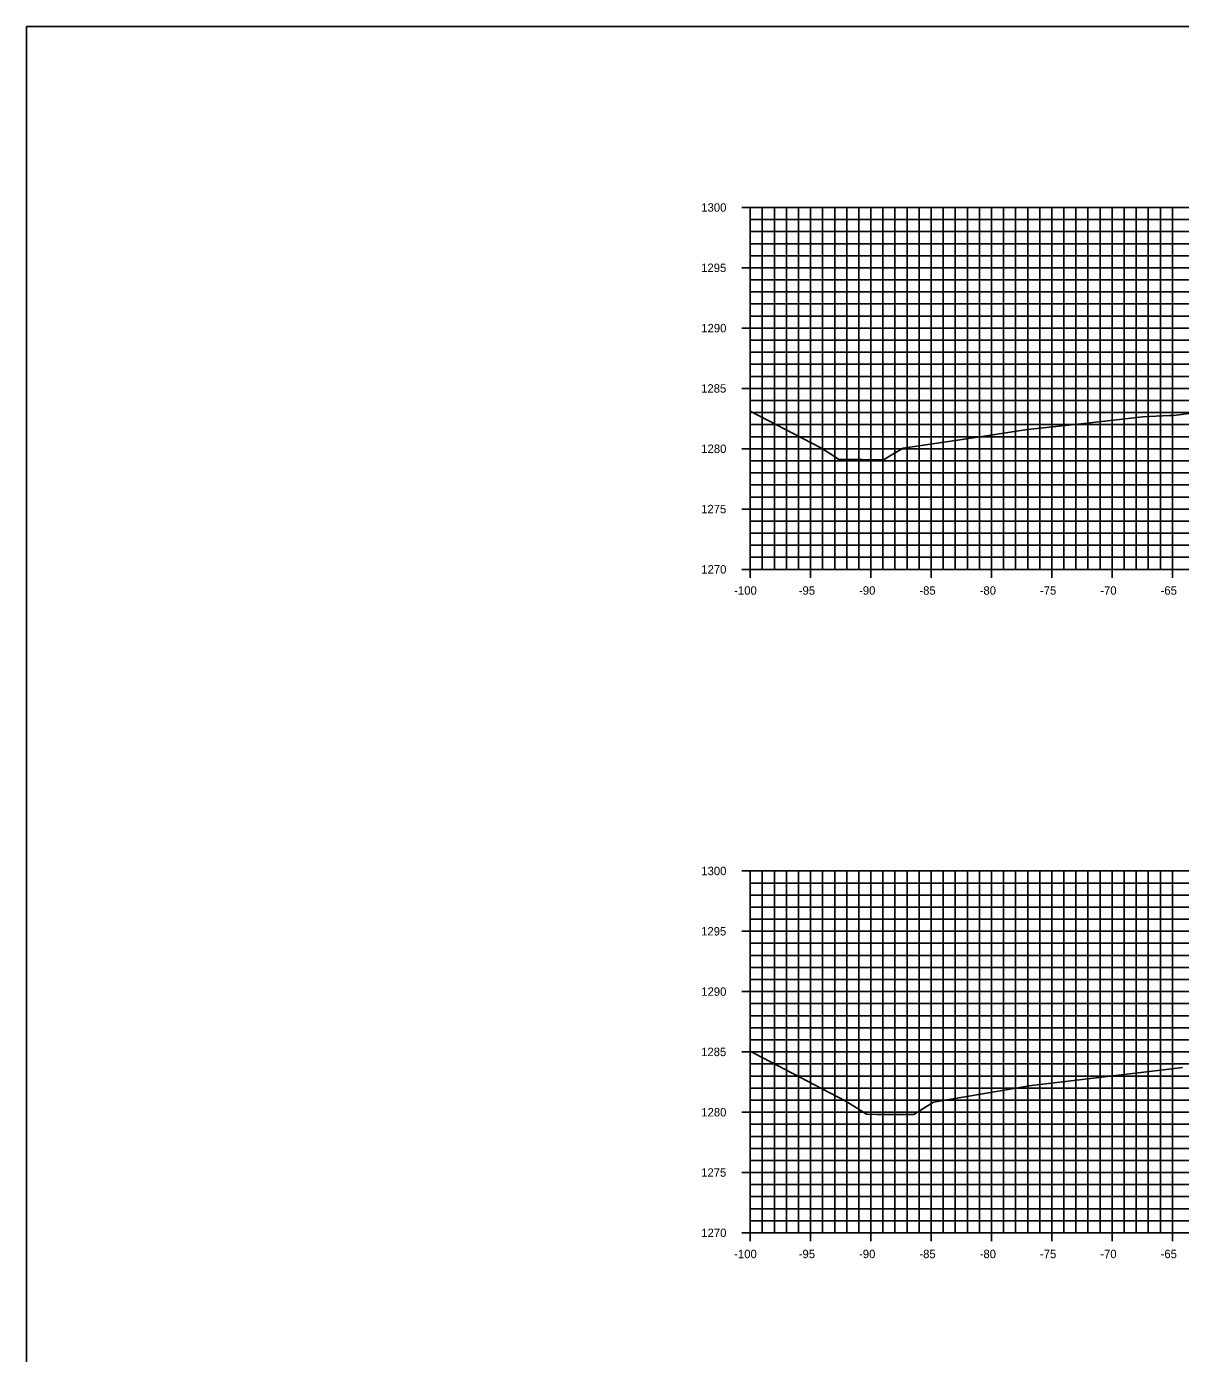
# Model space of a CAD drawing. Extents: x 674939 to 678919, y 750652 to 765176.
# Drawn here: x 678578.5 to 678674.2, y 755632.6 to 755742.6 of the extents above; entities that cross this region are included whole.
import ezdxf

# ---------------------------------------------------------------- set-up
doc = ezdxf.new("R2010")
doc.units = 0
for name, color, linetype in [('Level 10', 7, 'Continuous'), ('Level 20', 7, 'Continuous'), ('Level 4', 7, 'Continuous'), ('Level 8', 7, 'Continuous'), ('Level 9', 7, 'Continuous')]:
    doc.layers.add(name, color=color, linetype=linetype)

msp = doc.modelspace()

# ---------------------------------------------------------------- linework, layer by layer
at = {"layer": 'Level 10'}
for points in [[(678638.53, 755710.67), (678644.37, 755707.63), (678645.04, 755707.2), (678645.84, 755706.68), (678646.81, 755706.67), (678647.78, 755706.65), (678648.66, 755706.64), (678649.59, 755706.64), (678650.36, 755707.11), (678651.22, 755707.61), (678656.66, 755708.41), (678661.52, 755709.14), (678666.22, 755709.65), (678671.08, 755710.2), (678673.25, 755710.31), (678673.43, 755710.32), (678673.47, 755710.32), (678673.63, 755710.32), (678675.14, 755710.49)], [(678638.53, 755657.61), (678638.95, 755657.39), (678646.41, 755653.48), (678647.35, 755652.91), (678648.17, 755652.39), (678649.03, 755652.37), (678649.83, 755652.35), (678650.88, 755652.35), (678652.08, 755652.36), (678652.93, 755652.89), (678653.72, 755653.37), (678660.71, 755654.57), (678661.65, 755654.74), (678662.09, 755654.79), (678670.01, 755655.72), (678671.63, 755655.92), (678674.36, 755656.26)]]:
    msp.add_lwpolyline(points, dxfattribs=at)
at = {"layer": 'Level 20'}
for p, q in [((678638.53, 755727.55), (678838.53, 755727.55)), ((678638.53, 755697.55), (678638.53, 755727.55)), ((678639.53, 755697.55), (678639.53, 755727.55)), ((678640.53, 755697.55), (678640.53, 755727.55)), ((678641.53, 755697.55), (678641.53, 755727.55)), ((678642.53, 755697.55), (678642.53, 755727.55)), ((678643.53, 755697.55), (678643.53, 755727.55)), ((678644.53, 755697.55), (678644.53, 755727.55)), ((678645.53, 755697.55), (678645.53, 755727.55)), ((678646.53, 755697.55), (678646.53, 755727.55)), ((678647.53, 755697.55), (678647.53, 755727.55)), ((678648.53, 755697.55), (678648.53, 755727.55)), ((678649.53, 755697.55), (678649.53, 755727.55)), ((678650.53, 755697.55), (678650.53, 755727.55)), ((678651.53, 755697.55), (678651.53, 755727.55)), ((678652.53, 755697.55), (678652.53, 755727.55)), ((678653.53, 755697.55), (678653.53, 755727.55)), ((678654.53, 755697.55), (678654.53, 755727.55)), ((678655.53, 755697.55), (678655.53, 755727.55)), ((678656.53, 755697.55), (678656.53, 755727.55)), ((678657.53, 755697.55), (678657.53, 755727.55)), ((678658.53, 755697.55), (678658.53, 755727.55)), ((678659.53, 755697.55), (678659.53, 755727.55)), ((678660.53, 755697.55), (678660.53, 755727.55)), ((678661.53, 755697.55), (678661.53, 755727.55)), ((678662.53, 755697.55), (678662.53, 755727.55)), ((678663.53, 755697.55), (678663.53, 755727.55)), ((678664.53, 755697.55), (678664.53, 755727.55)), ((678665.53, 755697.55), (678665.53, 755727.55)), ((678666.53, 755697.55), (678666.53, 755727.55)), ((678667.53, 755697.55), (678667.53, 755727.55)), ((678668.53, 755697.55), (678668.53, 755727.55)), ((678669.53, 755697.55), (678669.53, 755727.55)), ((678670.53, 755697.55), (678670.53, 755727.55)), ((678671.53, 755697.55), (678671.53, 755727.55)), ((678672.53, 755697.55), (678672.53, 755727.55)), ((678673.53, 755697.55), (678673.53, 755727.55)), ((678638.53, 755726.55), (678838.53, 755726.55)), ((678638.53, 755725.55), (678838.53, 755725.55)), ((678638.53, 755724.55), (678838.53, 755724.55)), ((678638.53, 755723.55), (678838.53, 755723.55)), ((678638.53, 755722.55), (678838.53, 755722.55)), ((678638.53, 755721.55), (678838.53, 755721.55)), ((678638.53, 755720.55), (678838.53, 755720.55)), ((678638.53, 755719.55), (678838.53, 755719.55)), ((678638.53, 755718.55), (678838.53, 755718.55)), ((678638.53, 755717.55), (678838.53, 755717.55)), ((678638.53, 755716.55), (678838.53, 755716.55)), ((678638.53, 755715.55), (678838.53, 755715.55)), ((678638.53, 755714.55), (678838.53, 755714.55)), ((678638.53, 755713.55), (678838.53, 755713.55)), ((678638.53, 755712.55), (678838.53, 755712.55)), ((678638.53, 755711.55), (678838.53, 755711.55)), ((678638.53, 755710.55), (678838.53, 755710.55)), ((678638.53, 755709.55), (678838.53, 755709.55)), ((678638.53, 755708.55), (678838.53, 755708.55)), ((678638.53, 755707.55), (678838.53, 755707.55)), ((678638.53, 755706.55), (678838.53, 755706.55)), ((678638.53, 755705.55), (678838.53, 755705.55)), ((678638.53, 755704.55), (678838.53, 755704.55)), ((678638.53, 755703.55), (678838.53, 755703.55)), ((678638.53, 755702.55), (678838.53, 755702.55)), ((678638.53, 755701.55), (678838.53, 755701.55)), ((678638.53, 755700.55), (678838.53, 755700.55)), ((678638.53, 755699.55), (678838.53, 755699.55)), ((678638.53, 755698.55), (678838.53, 755698.55)), ((678638.53, 755697.55), (678838.53, 755697.55)), ((678638.53, 755672.55), (678838.53, 755672.55)), ((678638.53, 755642.55), (678638.53, 755672.55)), ((678639.53, 755642.55), (678639.53, 755672.55)), ((678640.53, 755642.55), (678640.53, 755672.55)), ((678641.53, 755642.55), (678641.53, 755672.55)), ((678642.53, 755642.55), (678642.53, 755672.55)), ((678643.53, 755642.55), (678643.53, 755672.55)), ((678644.53, 755642.55), (678644.53, 755672.55)), ((678645.53, 755642.55), (678645.53, 755672.55)), ((678646.53, 755642.55), (678646.53, 755672.55)), ((678647.53, 755642.55), (678647.53, 755672.55)), ((678648.53, 755642.55), (678648.53, 755672.55)), ((678649.53, 755642.55), (678649.53, 755672.55)), ((678650.53, 755642.55), (678650.53, 755672.55)), ((678651.53, 755642.55), (678651.53, 755672.55)), ((678652.53, 755642.55), (678652.53, 755672.55)), ((678653.53, 755642.55), (678653.53, 755672.55)), ((678654.53, 755642.55), (678654.53, 755672.55)), ((678655.53, 755642.55), (678655.53, 755672.55)), ((678656.53, 755642.55), (678656.53, 755672.55)), ((678657.53, 755642.55), (678657.53, 755672.55)), ((678658.53, 755642.55), (678658.53, 755672.55)), ((678659.53, 755642.55), (678659.53, 755672.55)), ((678660.53, 755642.55), (678660.53, 755672.55)), ((678661.53, 755642.55), (678661.53, 755672.55)), ((678662.53, 755642.55), (678662.53, 755672.55)), ((678663.53, 755642.55), (678663.53, 755672.55)), ((678664.53, 755642.55), (678664.53, 755672.55)), ((678665.53, 755642.55), (678665.53, 755672.55)), ((678666.53, 755642.55), (678666.53, 755672.55)), ((678667.53, 755642.55), (678667.53, 755672.55)), ((678668.53, 755642.55), (678668.53, 755672.55)), ((678669.53, 755642.55), (678669.53, 755672.55)), ((678670.53, 755642.55), (678670.53, 755672.55)), ((678671.53, 755642.55), (678671.53, 755672.55)), ((678672.53, 755642.55), (678672.53, 755672.55)), ((678673.53, 755642.55), (678673.53, 755672.55)), ((678638.53, 755671.55), (678838.53, 755671.55)), ((678638.53, 755670.55), (678838.53, 755670.55)), ((678638.53, 755669.55), (678838.53, 755669.55)), ((678638.53, 755668.55), (678838.53, 755668.55)), ((678638.53, 755667.55), (678838.53, 755667.55)), ((678638.53, 755666.55), (678838.53, 755666.55)), ((678638.53, 755665.55), (678838.53, 755665.55)), ((678638.53, 755664.55), (678838.53, 755664.55)), ((678638.53, 755663.55), (678838.53, 755663.55)), ((678638.53, 755662.55), (678838.53, 755662.55)), ((678638.53, 755661.55), (678838.53, 755661.55)), ((678638.53, 755660.55), (678838.53, 755660.55)), ((678638.53, 755659.55), (678838.53, 755659.55)), ((678638.53, 755658.55), (678838.53, 755658.55)), ((678638.53, 755657.55), (678838.53, 755657.55)), ((678638.53, 755656.55), (678838.53, 755656.55)), ((678638.53, 755655.55), (678838.53, 755655.55)), ((678638.53, 755654.55), (678838.53, 755654.55)), ((678638.53, 755653.55), (678838.53, 755653.55)), ((678638.53, 755652.55), (678838.53, 755652.55)), ((678638.53, 755651.55), (678838.53, 755651.55)), ((678638.53, 755650.55), (678838.53, 755650.55)), ((678638.53, 755649.55), (678838.53, 755649.55)), ((678638.53, 755648.55), (678838.53, 755648.55)), ((678638.53, 755647.55), (678838.53, 755647.55)), ((678638.53, 755646.55), (678838.53, 755646.55)), ((678638.53, 755645.55), (678838.53, 755645.55)), ((678638.53, 755644.55), (678838.53, 755644.55)), ((678638.53, 755643.55), (678838.53, 755643.55)), ((678638.53, 755642.55), (678838.53, 755642.55))]:
    msp.add_line(p, q, dxfattribs=at)
at = {"layer": 'Level 4'}
msp.add_lwpolyline([(678578.53, 755522.55), (678918.53, 755522.55), (678918.53, 755742.55), (678578.53, 755742.55)], close=True, dxfattribs=at)
at = {"layer": 'Level 8'}
for p, q in [((678637.83, 755727.55), (678639.23, 755727.55)), ((678638.53, 755697.55), (678638.53, 755727.55)), ((678638.53, 755726.55), (678638.88, 755726.55)), ((678638.53, 755725.55), (678638.88, 755725.55)), ((678638.53, 755724.55), (678638.88, 755724.55)), ((678638.53, 755723.55), (678638.88, 755723.55)), ((678637.83, 755722.55), (678639.23, 755722.55)), ((678638.53, 755721.55), (678638.88, 755721.55)), ((678638.53, 755720.55), (678638.88, 755720.55)), ((678638.53, 755719.55), (678638.88, 755719.55)), ((678638.53, 755718.55), (678638.88, 755718.55)), ((678637.83, 755717.55), (678639.23, 755717.55)), ((678638.53, 755716.55), (678638.88, 755716.55)), ((678638.53, 755715.55), (678638.88, 755715.55)), ((678638.53, 755714.55), (678638.88, 755714.55)), ((678638.53, 755713.55), (678638.88, 755713.55)), ((678637.83, 755712.55), (678639.23, 755712.55)), ((678638.53, 755711.55), (678638.88, 755711.55)), ((678638.53, 755710.55), (678638.88, 755710.55)), ((678638.53, 755709.55), (678638.88, 755709.55)), ((678638.53, 755708.55), (678638.88, 755708.55)), ((678637.83, 755707.55), (678639.23, 755707.55)), ((678638.53, 755706.55), (678638.88, 755706.55)), ((678638.53, 755705.55), (678638.88, 755705.55)), ((678638.53, 755704.55), (678638.88, 755704.55)), ((678638.53, 755703.55), (678638.88, 755703.55)), ((678637.83, 755702.55), (678639.23, 755702.55)), ((678638.53, 755701.55), (678638.88, 755701.55)), ((678638.53, 755700.55), (678638.88, 755700.55)), ((678638.53, 755699.55), (678638.88, 755699.55)), ((678638.53, 755698.55), (678638.88, 755698.55)), ((678638.53, 755696.85), (678638.53, 755698.25)), ((678643.53, 755696.85), (678643.53, 755698.25)), ((678648.53, 755696.85), (678648.53, 755698.25)), ((678653.53, 755696.85), (678653.53, 755698.25)), ((678658.53, 755696.85), (678658.53, 755698.25)), ((678663.53, 755696.85), (678663.53, 755698.25)), ((678668.53, 755696.85), (678668.53, 755698.25)), ((678673.53, 755696.85), (678673.53, 755698.25)), ((678637.83, 755697.55), (678639.23, 755697.55)), ((678638.53, 755697.55), (678838.53, 755697.55)), ((678637.83, 755672.55), (678639.23, 755672.55)), ((678638.53, 755642.55), (678638.53, 755672.55)), ((678638.53, 755671.55), (678638.88, 755671.55)), ((678638.53, 755670.55), (678638.88, 755670.55)), ((678638.53, 755669.55), (678638.88, 755669.55)), ((678638.53, 755668.55), (678638.88, 755668.55)), ((678637.83, 755667.55), (678639.23, 755667.55)), ((678638.53, 755666.55), (678638.88, 755666.55)), ((678638.53, 755665.55), (678638.88, 755665.55)), ((678638.53, 755664.55), (678638.88, 755664.55)), ((678638.53, 755663.55), (678638.88, 755663.55)), ((678637.83, 755662.55), (678639.23, 755662.55)), ((678638.53, 755661.55), (678638.88, 755661.55)), ((678638.53, 755660.55), (678638.88, 755660.55)), ((678638.53, 755659.55), (678638.88, 755659.55)), ((678638.53, 755658.55), (678638.88, 755658.55)), ((678637.83, 755657.55), (678639.23, 755657.55)), ((678638.53, 755656.55), (678638.88, 755656.55)), ((678638.53, 755655.55), (678638.88, 755655.55)), ((678638.53, 755654.55), (678638.88, 755654.55)), ((678638.53, 755653.55), (678638.88, 755653.55)), ((678637.83, 755652.55), (678639.23, 755652.55)), ((678638.53, 755651.55), (678638.88, 755651.55)), ((678638.53, 755650.55), (678638.88, 755650.55)), ((678638.53, 755649.55), (678638.88, 755649.55)), ((678638.53, 755648.55), (678638.88, 755648.55)), ((678637.83, 755647.55), (678639.23, 755647.55)), ((678638.53, 755646.55), (678638.88, 755646.55)), ((678638.53, 755645.55), (678638.88, 755645.55)), ((678638.53, 755644.55), (678638.88, 755644.55)), ((678638.53, 755643.55), (678638.88, 755643.55)), ((678638.53, 755641.85), (678638.53, 755643.25)), ((678643.53, 755641.85), (678643.53, 755643.25)), ((678648.53, 755641.85), (678648.53, 755643.25)), ((678653.53, 755641.85), (678653.53, 755643.25)), ((678658.53, 755641.85), (678658.53, 755643.25)), ((678663.53, 755641.85), (678663.53, 755643.25)), ((678668.53, 755641.85), (678668.53, 755643.25)), ((678673.53, 755641.85), (678673.53, 755643.25)), ((678637.83, 755642.55), (678639.23, 755642.55)), ((678638.53, 755642.55), (678838.53, 755642.55))]:
    msp.add_line(p, q, dxfattribs=at)

# ---------------------------------------------------------------- texts
at = {"layer": 'Level 9'}
for s, p in [('1300', (678634.47, 755727.2)), ('1295', (678634.46, 755722.2)), ('1290', (678634.47, 755717.2)), ('1285', (678634.46, 755712.2)), ('1280', (678634.47, 755707.2)), ('1275', (678634.46, 755702.2)), ('1270', (678634.47, 755697.2)), ('-100', (678637.2, 755695.45)), ('-95', (678642.55, 755695.45)), ('-90', (678647.55, 755695.45)), ('-85', (678652.55, 755695.45)), ('-80', (678657.55, 755695.45)), ('-75', (678662.55, 755695.45)), ('-70', (678667.55, 755695.45)), ('-65', (678672.55, 755695.45)), ('1300', (678634.47, 755672.2)), ('1295', (678634.46, 755667.2)), ('1290', (678634.47, 755662.2)), ('1285', (678634.46, 755657.2)), ('1280', (678634.47, 755652.2)), ('1275', (678634.46, 755647.2)), ('1270', (678634.47, 755642.2)), ('-100', (678637.2, 755640.45)), ('-95', (678642.55, 755640.45)), ('-90', (678647.55, 755640.45)), ('-85', (678652.55, 755640.45)), ('-80', (678657.55, 755640.45)), ('-75', (678662.55, 755640.45)), ('-70', (678667.55, 755640.45)), ('-65', (678672.55, 755640.45))]:
    msp.add_text(s, height=0.7, dxfattribs=at).set_placement(p)

doc.saveas('drawing.dxf')
